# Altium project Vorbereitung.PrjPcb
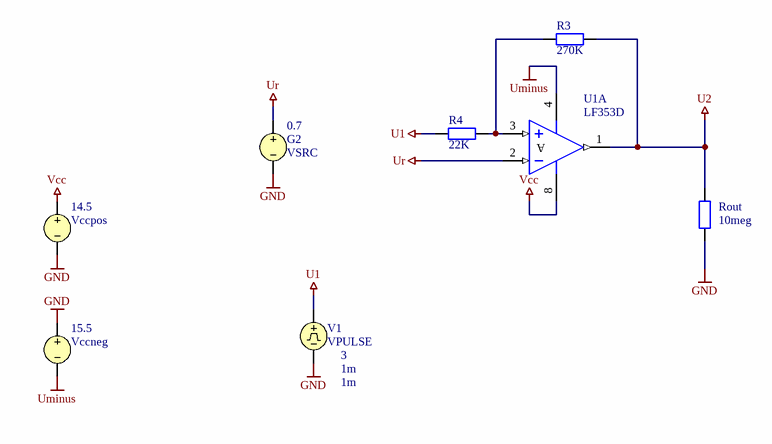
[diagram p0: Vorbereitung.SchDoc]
2 sheets, 17 parts. Net scope: global (net labels, ports and power ports of the same name join across sheets).
Sheets:
  Vorbereitung.SchDoc
  protokollschametic.SchDoc

## Sheet Vorbereitung.SchDoc
size A4

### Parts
(Parts that share a designator on the sheet are numbered #1, #2 ... from top to bottom, then left to right.)
G2  VSRC  value 0.7
R3#1  value 270K  [AXIAL-0.4]  (hidden comment: Res2)
R4#1  value 22K  [AXIAL-0.4]  (hidden comment: Res2)
Rout  value 10meg  [AXIAL-0.4]  (hidden comment: Res2)
U1  LF353D  [D008_L]  (part A of 2)
V1  VPULSE  AC Magnitude: 3  Rise Time: 1m
Vccneg  value 15.5  (hidden comment: VSRC)
Vccpos  value 14.5  (hidden comment: VSRC)

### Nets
GND: G2.2 Rout.1 V1.2 Vccneg.1 Vccpos.2
U1: R4#1.2 V1.1
U2: R3#1.1 Rout.2 U1.1(OUT)
Uminus: U1.4(V-) Vccneg.2
Ur: G2.1 U1.2(IN-)
Vcc: U1.8(V+) Vccpos.1
NetR3#1_2: R3#1.2 R4#1.1 U1.3(IN+)

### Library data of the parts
G2 Vccneg Vccpos = VSRC: Voltage Source; Note: PCB Footprint - Not required
R3#1 R4#1 Rout = Res2: Resistor
U1 = LF353D: Dual Operational Amplifier
V1 = VPULSE: Pulse Voltage Source; Note: PCB Footprint - Not required

## Sheet protokollschametic.SchDoc
size A4; PageSetup: Record=PageOptions¦CenterHorizontal=True¦CenterVertical=True¦PrintScale=0.87¦XCorrection=1.00¦YCorrection=1.00¦PrintKind=2¦BorderSize=5000000¦LeftOffset=0¦BottomOffset=0¦Orientation=2¦PaperLength=1000¦PaperWidth=1000¦Scale=100¦PaperSource=7¦PrintQuality=-4¦MediaType=1¦DitherType=10¦PaperKind=Letter¦PrintScaleMode=1
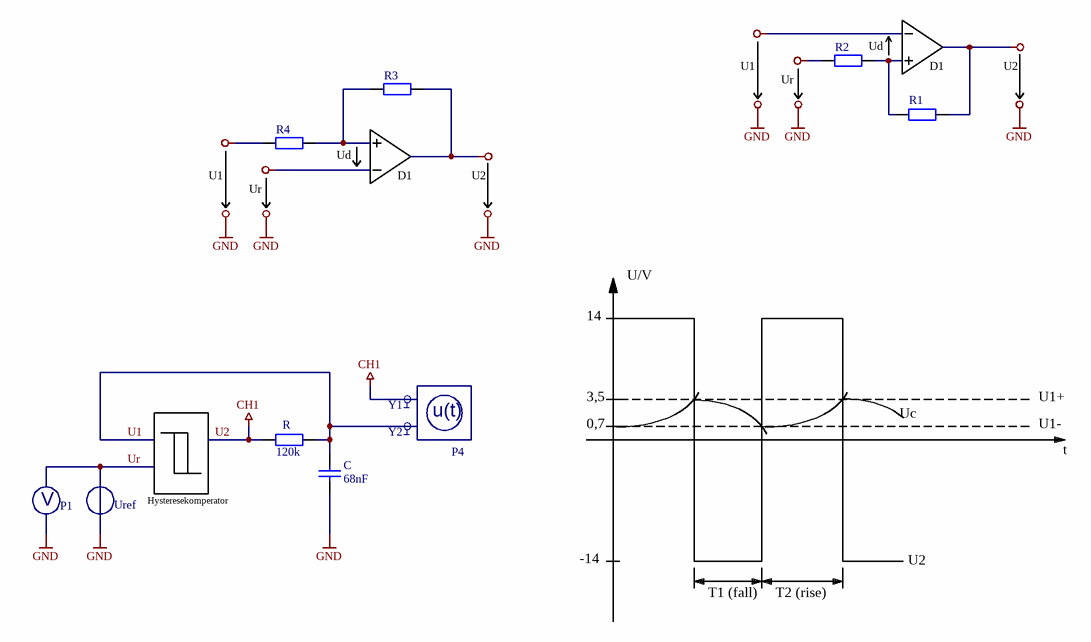
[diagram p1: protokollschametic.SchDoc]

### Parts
(Parts that share a designator on the sheet are numbered #1, #2 ... from top to bottom, then left to right.)
C  value 68nF  [RAD-0.3]  (hidden comment: Cap)
P1  Voltmeter1  (value not drawn)
P4  Oszilloskop2Kanal  (value not drawn)
R  value 120k  [AXIAL-0.4]  (hidden comment: Res2)
R1  Res2  [AXIAL-0.4]  (value not drawn)
R2  Res2  [AXIAL-0.4]  (value not drawn)
R3#2  Res2  [AXIAL-0.4]  (value not drawn)
R4#2  Res2  [AXIAL-0.4]  (value not drawn)
Uref  Spannungsquelle  (value not drawn)

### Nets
GND: C.1 P1.2 R1.2 R2.1 R3#2.2 R4#2.1 Uref.2
U1: C.2 P4.2 R.2
U2: P4.1 R.1  [also labelled CH1]
Ur: P1.1 Uref.1
NetR1_1: R1.1 R2.2
NetR3#2_1: R3#2.1 R4#2.2

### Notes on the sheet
- U1
- (near R2) Ur
- (near R2) Ud
- (near R1) D1
- U2
- (near R4#2) Ud
- (near R4#2) Ur
- D1
- U/V
- 14
- 0,7
- 3,5
- Uc
- U1+
- U1-
- Hysteresekomperator
- t
- -14
- T1 (fall)
- T2 (rise)

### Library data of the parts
C = Cap: Capacitor
R = Res2: Resistor
R1 R2 R3#2 R4#2 = Res2: Resistor; Value: 1K

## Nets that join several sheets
GND: Vorbereitung (5 pins), protokollschametic (7 pins)
U1: Vorbereitung (R4#1.2 V1.1), protokollschametic (C.2 P4.2 R.2)
U2: Vorbereitung (R3#1.1 Rout.2 U1.1), protokollschametic (P4.1 R.1)
Ur: Vorbereitung (G2.1 U1.2), protokollschametic (P1.1 Uref.1)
